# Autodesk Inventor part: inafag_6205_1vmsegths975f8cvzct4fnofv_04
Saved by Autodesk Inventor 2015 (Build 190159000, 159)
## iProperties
Company: TraceParts S.A.
Created: 2012-12
Part Number: inafag_6205_1vmsegths975f8cvzct4fnofv_04
Checked By: TraceParts S.A.
Catalog Web Link: www.traceparts.com
Document SubType Name: Modeling
Designer: TraceParts
Material: Generic
Density: 1 g/cm^3
Appearance: Default
Author: TraceParts
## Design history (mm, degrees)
feature "inafag_6205_1vmsegths975f8cvzct4fnofv"
body "Solid1"
